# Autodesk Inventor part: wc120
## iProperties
Shininess: 64.0
Length Units: 11272
Angle Units: 11279
Time Units: 11290
Mass Units: 11286
Length Display Precision: 3
Angle Display Precision: 2
Compacted: True
Part Number: wc120
Document SubType Name: Modeling
Created: 2004-08
Designer: John Blackburn
Manufacturer: Standard
Standards Organization: Custom
Density: 0.0
Volumn: 0.0
Area: 0.0
PropertySet Name: Model Information
Control State: 0
Master: False
Checked Out: False
Author: John Blackburn
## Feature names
1. Base1
